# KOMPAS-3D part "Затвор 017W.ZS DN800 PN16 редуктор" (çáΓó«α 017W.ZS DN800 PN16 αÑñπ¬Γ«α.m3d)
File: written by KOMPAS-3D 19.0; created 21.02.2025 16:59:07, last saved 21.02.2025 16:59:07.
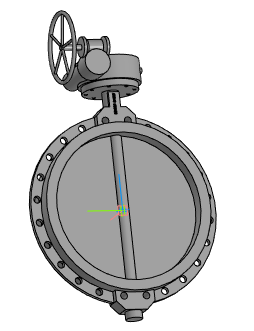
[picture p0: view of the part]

Document properties: Автор: Евгений; Полное имя файла: Затвор 017W.ZS DN800 PN16 редуктор.a3d

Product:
- Part/product: Затвор 017W.ZS DN800 PN16 редуктор
    Масса: 541.349

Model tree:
1. Операция без истории:1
